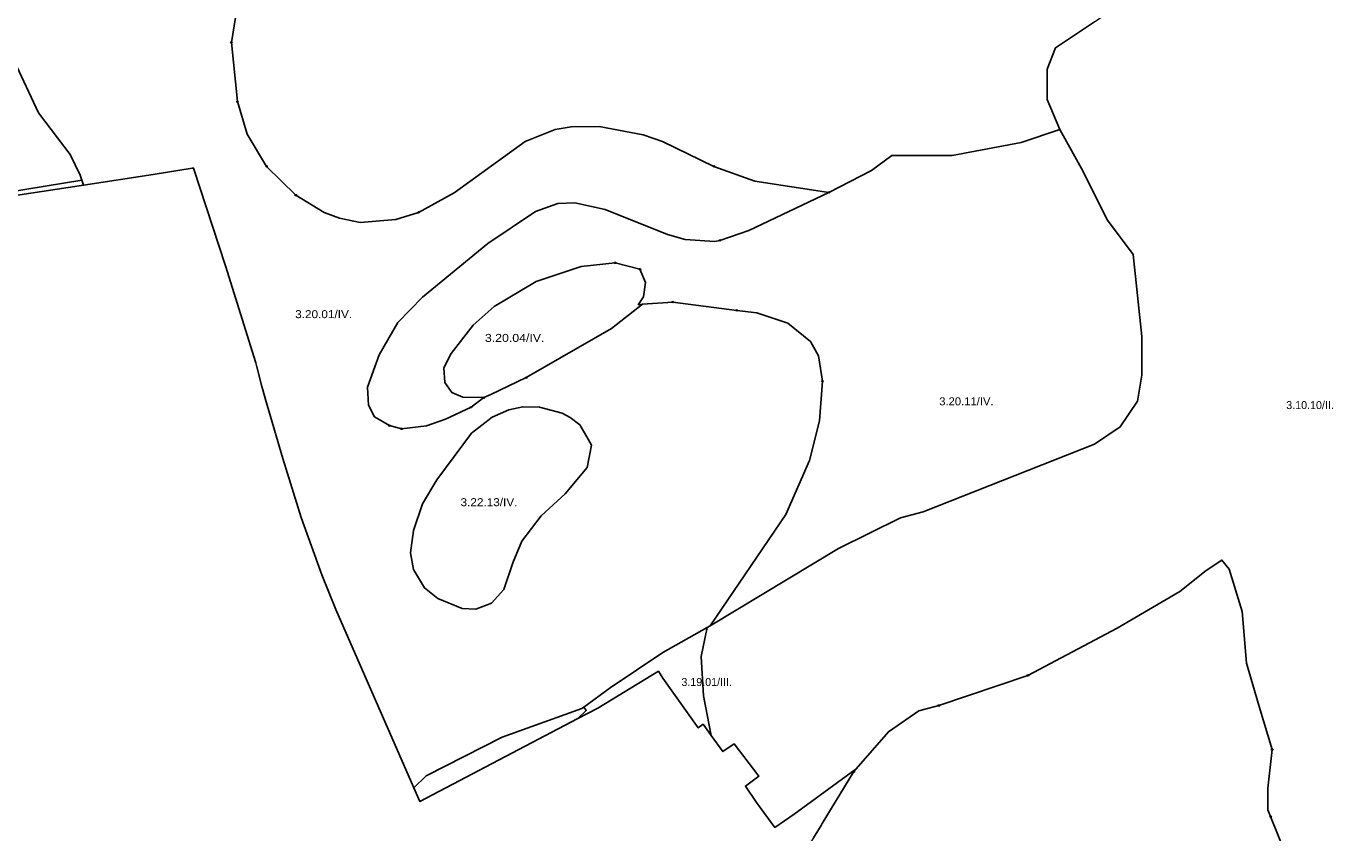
# Model space of a CAD drawing. Extents: x -650455 to -642254, y -1075222 to -1066610.
# Drawn here: x -649362 to -647729, y -1071216 to -1070208 of the extents above; entities that cross this region are included whole.
import ezdxf
from ezdxf.enums import TextEntityAlignment as Align

# ---------------------------------------------------------------- set-up
doc = ezdxf.new("R2010")
doc.units = 0
doc.header["$LTSCALE"] = 4
doc.header["$PDMODE"] = 32
doc.header["$PDSIZE"] = 2
for name, color, linetype, lineweight in [('1', 7, 'Continuous', 25), ('11', 7, 'Continuous', 13), ('12', 7, 'Continuous', 13), ('13', 7, 'Continuous', 13), ('14', 7, 'Continuous', 13)]:
    doc.layers.add(name, color=color, linetype=linetype, lineweight=lineweight)
doc.layers.add('2', color=7, linetype='Continuous')

msp = doc.modelspace()

# ---------------------------------------------------------------- linework, layer by layer
at = {"layer": '1'}
for points in [[(-649095, -1070162.5), (-649105.5, -1070228.001), (-649098, -1070302.001), (-649086, -1070342.501), (-649061.5, -1070383.001), (-649025, -1070419.001), (-648989.5, -1070440.5), (-648970.5, -1070447.501), (-648944.5, -1070453), (-648900, -1070449.5), (-648871.5, -1070440.5), (-648827, -1070416), (-648738.5, -1070352), (-648701, -1070337), (-648681, -1070333.501), (-648646, -1070333.001), (-648591, -1070343.5), (-648567, -1070352), (-648502.5, -1070383.001), (-648451.5, -1070401.5), (-648359, -1070415.501), (-648459, -1070463.001), (-648495, -1070475.501), (-648501.5, -1070477), (-648538.5, -1070474.5), (-648560.5, -1070468.001), (-648638.5, -1070437), (-648676.5, -1070428.5), (-648697.5, -1070429.5), (-648725.5, -1070439.501), (-648785, -1070479.501)], [(-648426.267, -1071209.383), (-648449.154, -1071178.032), (-648463.238, -1071157.601), (-648446.337, -1071145.271), (-648477.322, -1071104.762), (-648491.406, -1071114.625), (-648506.045, -1071094.331), (-648515.5, -1071045), (-648518.5, -1070995.5), (-648511, -1070959.5), (-648507.369, -1070957.309), (-648347, -1070860.501), (-648269.5, -1070822.5), (-648241, -1070815.001), (-648027.074, -1070730.177), (-647994.757, -1070708.632), (-647973.213, -1070676.315), (-647967.826, -1070643.998), (-647967.826, -1070595.523), (-647978.599, -1070493.186), (-648010.916, -1070450.096), (-648043.233, -1070385.463), (-648070.164, -1070336.987), (-648086.322, -1070299.284), (-648086.322, -1070261.581), (-648075.55, -1070234.65), (-648027.074, -1070202.333)], [(-649377, -1070251), (-649346.5, -1070316), (-649307, -1070368), (-649294.5, -1070394.001), (-649292.5, -1070400), (-649384, -1070415.001)], [(-649041.195, -1070748.176), (-649062.695, -1070674.37), (-649066.192, -1070662.363), (-649067.279, -1070658.191), (-649073.701, -1070633.531), (-649074.607, -1070630.05), (-649074.998, -1070628.551), (-649113.062, -1070507.22), (-649152.827, -1070384.991), (-649154.468, -1070385.26), (-649203.149, -1070393.237), (-649290.153, -1070406.417), (-649292.5, -1070400), (-649294.5, -1070394.001), (-649307, -1070368), (-649346.5, -1070316), (-649377, -1070251)], [(-648725.5, -1070439.501), (-648697.5, -1070429.5), (-648676.5, -1070428.5), (-648638.5, -1070437), (-648560.5, -1070468.001), (-648538.5, -1070474.5), (-648501.5, -1070477), (-648495, -1070475.501), (-648459, -1070463.001), (-648359, -1070415.501), (-648305.5, -1070388), (-648280.182, -1070369.304), (-648204.818, -1070369.304), (-648118.639, -1070353.145), (-648070.164, -1070336.987), (-648043.233, -1070385.463), (-648010.916, -1070450.096), (-647978.599, -1070493.186), (-647967.826, -1070595.523), (-647967.826, -1070643.998), (-647973.213, -1070676.315), (-647994.757, -1070708.632), (-648027.074, -1070730.177), (-648241, -1070815.001), (-648269.5, -1070822.5), (-648347, -1070860.501), (-648507.369, -1070957.309)], [(-648507.369, -1070957.309), (-648412.5, -1070818), (-648383, -1070750.501), (-648370.5, -1070701), (-648367, -1070651.5), (-648372, -1070620), (-648382, -1070602.001), (-648410, -1070579), (-648449, -1070566), (-648474, -1070563), (-648554, -1070552.501), (-648592, -1070555), (-648597, -1070556.001), (-648590.5, -1070546), (-648588, -1070528.001), (-648595, -1070511.501), (-648626, -1070503.501), (-648668.5, -1070508.001), (-648724.5, -1070527), (-648777, -1070558), (-648803.5, -1070581.501), (-648831, -1070617.001), (-648840, -1070635), (-648839, -1070653.001), (-648830, -1070665.501), (-648816.5, -1070671.5), (-648790, -1070672), (-648806, -1070684), (-648838, -1070699.001), (-648861.5, -1070707.5), (-648893, -1070711.001), (-648908, -1070707.001), (-648926.5, -1070696), (-648934, -1070681.501), (-648935.5, -1070659), (-648921, -1070618.5), (-648897.5, -1070578), (-648866.5, -1070546.5), (-648785, -1070479.501), (-648725.5, -1070439.501)], [(-648785, -1070479.501), (-648866.5, -1070546.5), (-648897.5, -1070578), (-648921, -1070618.5), (-648935.5, -1070659), (-648934, -1070681.501), (-648926.5, -1070696), (-648908, -1070707.001), (-648893, -1070711.001), (-648861.5, -1070707.5), (-648838, -1070699.001), (-648806, -1070684), (-648790, -1070672), (-648781.5, -1070668), (-648737, -1070647), (-648630.5, -1070585.501), (-648592, -1070555), (-648554, -1070552.501), (-648474, -1070563), (-648449, -1070566), (-648410, -1070579), (-648382, -1070602.001), (-648372, -1070620), (-648367, -1070651.5), (-648370.5, -1070701), (-648383, -1070750.501), (-648412.5, -1070818), (-648507.369, -1070957.309), (-648511, -1070959.5), (-648566.5, -1070990.501), (-648632, -1071035.001), (-648665, -1071059.001), (-648667.5, -1071060.5), (-648767, -1071096.5), (-648862, -1071145), (-648877.384, -1071160.07), (-648975.147, -1070936.986), (-648992.621, -1070893.659), (-649018.47, -1070821.77), (-649041.195, -1070748.176)], [(-647788.736, -1071241.189), (-647806.937, -1071195.687), (-647810.281, -1071187.327), (-647810.281, -1071160.397), (-647804.895, -1071111.921), (-647821.053, -1071058.06), (-647837.212, -1071004.198), (-647842.598, -1070939.564), (-647858.53, -1070886.459), (-647867.716, -1070875.174), (-647887.378, -1070888.282), (-647920.15, -1070914.5), (-647998.802, -1070960.38), (-648110.225, -1071019.369), (-648221.5, -1071057), (-648246.5, -1071063.501), (-648284.5, -1071090), (-648327.713, -1071139.525), (-648326.269, -1071137.169), (-648402.324, -1071192.827), (-648426.267, -1071209.383)], [(-648378.097, -1071222.492), (-648368.619, -1071206.983), (-648367.47, -1071204.399), (-648327.713, -1071139.525), (-648284.5, -1071090), (-648246.5, -1071063.501), (-648221.5, -1071057), (-648110.225, -1071019.369), (-647998.802, -1070960.38), (-647920.15, -1070914.5), (-647887.378, -1070888.282), (-647867.716, -1070875.174), (-647858.53, -1070886.459), (-647842.598, -1070939.564), (-647837.212, -1071004.198)], [(-647837.212, -1071004.198), (-647821.053, -1071058.06), (-647804.895, -1071111.921), (-647810.281, -1071160.397), (-647810.281, -1071187.327), (-647806.937, -1071195.687), (-647788.736, -1071241.189)]]:
    msp.add_lwpolyline(points, dxfattribs=at)
for points in [[(-649292.5, -1070400), (-649290.153, -1070406.417), (-649441.654, -1070429.367), (-649547.261, -1070444.531), (-649548.761, -1070444.745), (-649561.895, -1070448.418), (-649615.231, -1070460.576), (-649617.552, -1070460.168), (-649621.118, -1070460.078), (-649621.21, -1070460.1), (-649621, -1070441), (-649622.5, -1070387.501), (-649635.5, -1070354.001), (-649653, -1070326.501), (-649662, -1070295), (-649546, -1070342.501), (-649404.5, -1070412.5), (-649384, -1070415.001)], [(-648592, -1070555), (-648630.5, -1070585.501), (-648737, -1070647), (-648781.5, -1070668), (-648790, -1070672), (-648816.5, -1070671.5), (-648830, -1070665.501), (-648839, -1070653.001), (-648840, -1070635), (-648831, -1070617.001), (-648803.5, -1070581.501), (-648777, -1070558), (-648724.5, -1070527), (-648668.5, -1070508.001), (-648626, -1070503.501), (-648595, -1070511.501), (-648588, -1070528.001), (-648590.5, -1070546), (-648597, -1070556.001)], [(-648780.5, -1070929.001), (-648765, -1070912.001), (-648754, -1070878.5), (-648742.5, -1070851.501), (-648718.5, -1070820.001), (-648688.5, -1070792.5), (-648661, -1070759.501), (-648655.5, -1070731.501), (-648659.5, -1070724), (-648670, -1070706.001), (-648682, -1070697), (-648692, -1070691.5), (-648720.5, -1070684), (-648741.5, -1070683.5), (-648759, -1070687.5), (-648779.5, -1070696.5), (-648805.5, -1070716.5), (-648849, -1070775.001), (-648866.5, -1070805), (-648878, -1070838), (-648881.5, -1070866), (-648878, -1070887), (-648864, -1070910), (-648847.5, -1070923), (-648817, -1070935.5), (-648800, -1070936.501)], [(-648780.5, -1070929.001), (-648800, -1070936.501), (-648817, -1070935.5), (-648847.5, -1070923), (-648864, -1070910), (-648878, -1070887), (-648881.5, -1070866), (-648878, -1070838), (-648866.5, -1070805), (-648849, -1070775.001), (-648805.5, -1070716.5), (-648779.5, -1070696.5), (-648759, -1070687.5), (-648741.5, -1070683.5), (-648720.5, -1070684), (-648692, -1070691.5), (-648682, -1070697), (-648670, -1070706.001), (-648659.5, -1070724), (-648655.5, -1070731.501), (-648661, -1070759.501), (-648688.5, -1070792.5), (-648718.5, -1070820.001), (-648742.5, -1070851.501), (-648754, -1070878.5), (-648765, -1070912.001)], [(-648518.5, -1070995.5), (-648515.5, -1071045), (-648506.045, -1071094.331), (-648516.053, -1071080.457), (-648522.391, -1071084.685), (-648566.404, -1071022.688), (-648571.8, -1071014.049), (-648647.789, -1071060.362), (-648672.55, -1071073.359), (-648662, -1071063.001), (-648665, -1071059.001), (-648632, -1071035.001), (-648566.5, -1070990.501), (-648511, -1070959.5)], [(-648672.55, -1071073.359), (-648869.971, -1071176.986), (-648877.384, -1071160.07), (-648862, -1071145), (-648767, -1071096.5), (-648667.5, -1071060.5), (-648665, -1071059.001), (-648662, -1071063.001)]]:
    msp.add_lwpolyline(points, close=True, dxfattribs=at)
at = {"layer": '11'}
for p, q in [((-649105.5, -1070228.001), (-649098, -1070302.001)), ((-647788.736, -1071241.189), (-647806.937, -1071195.687))]:
    msp.add_line(p, q, dxfattribs=at)
for points in [[(-648819.5, -1069761), (-648791.5, -1069782), (-648774.5, -1069810), (-648769, -1069831.501), (-648772.5, -1069872.001), (-648781.5, -1069894.5), (-648808.5, -1069926), (-648853, -1069952.501), (-648883.5, -1069962.5), (-648919, -1069968.5), (-648912.614, -1070000), (-648911.5, -1070005.501), (-648918, -1070020.5), (-648942, -1070040), (-648979.5, -1070057), (-649008, -1070070.001), (-649053.5, -1070100.001), (-649085, -1070140.001), (-649095, -1070162.5), (-649105.5, -1070228.001)], [(-648359, -1070415.501), (-648305.5, -1070388), (-648280.182, -1070369.304), (-648204.818, -1070369.304), (-648118.639, -1070353.145), (-648070.164, -1070336.987), (-648086.322, -1070299.284), (-648086.322, -1070261.581), (-648075.55, -1070234.65), (-648027.074, -1070202.333), (-647998.797, -1070182.808)], [(-649098, -1070302.001), (-649086, -1070342.501), (-649061.5, -1070383.001), (-649025, -1070419.001)], [(-649025, -1070419.001), (-648989.5, -1070440.5), (-648970.5, -1070447.501), (-648944.5, -1070453), (-648900, -1070449.5), (-648871.5, -1070440.5), (-648827, -1070416), (-648738.5, -1070352), (-648701, -1070337), (-648681, -1070333.501), (-648646, -1070333.001), (-648591, -1070343.5), (-648567, -1070352), (-648502.5, -1070383.001)], [(-648502.5, -1070383.001), (-648451.5, -1070401.5), (-648359, -1070415.501)], [(-647804.895, -1071111.921), (-647821.053, -1071058.06), (-647837.212, -1071004.198), (-647842.598, -1070939.564), (-647858.53, -1070886.459), (-647867.716, -1070875.174), (-647887.378, -1070888.282), (-647920.15, -1070914.5), (-647998.802, -1070960.38), (-648110.225, -1071019.369)], [(-648110.225, -1071019.369), (-648221.5, -1071057), (-648246.5, -1071063.501), (-648284.5, -1071090), (-648327.713, -1071139.525)], [(-647806.937, -1071195.687), (-647810.281, -1071187.327), (-647810.281, -1071160.397), (-647804.895, -1071111.921)], [(-648327.713, -1071139.525), (-648367.47, -1071204.399), (-648368.619, -1071206.983), (-648378.097, -1071222.492), (-648386.713, -1071235.418), (-648397.483, -1071253.511), (-648410.551, -1071274.192), (-648413.28, -1071279.36), (-648415.434, -1071281.946), (-648421.035, -1071292.285), (-648502.316, -1071458.869), (-648515.528, -1071484.719), (-648550.69, -1071556.284)]]:
    msp.add_lwpolyline(points, dxfattribs=at)
at = {"layer": '11', "lineweight": 25}
for points in [[(-648280.182, -1070369.304), (-648305.5, -1070388), (-648359, -1070415.501), (-648451.5, -1070401.5), (-648502.5, -1070383.001), (-648567, -1070352), (-648591, -1070343.5), (-648646, -1070333.001), (-648681, -1070333.501), (-648701, -1070337), (-648738.5, -1070352), (-648827, -1070416), (-648871.5, -1070440.5), (-648900, -1070449.5), (-648944.5, -1070453), (-648970.5, -1070447.501), (-648989.5, -1070440.5), (-649025, -1070419.001), (-649061.5, -1070383.001), (-649086, -1070342.501), (-649098, -1070302.001), (-649105.5, -1070228.001), (-649095, -1070162.5)], [(-648027.074, -1070202.333), (-648075.55, -1070234.65), (-648086.322, -1070261.581), (-648086.322, -1070299.284), (-648070.164, -1070336.987), (-648118.639, -1070353.145), (-648204.818, -1070369.304), (-648280.182, -1070369.304)]]:
    msp.add_lwpolyline(points, dxfattribs=at)
at = {"layer": '11'}
for p in [(-649105.5, -1070228.001), (-649098, -1070302.001), (-648502.5, -1070383.001), (-649025, -1070419.001), (-648359, -1070415.501), (-648110.225, -1071019.369), (-647804.895, -1071111.921), (-648327.713, -1071139.525), (-647806.937, -1071195.687)]:
    msp.add_point(p, dxfattribs=at)
at = {"layer": '12'}
msp.add_line((-648221.5, -1071057), (-648110.225, -1071019.369), dxfattribs=at)
for points in [[(-648027.074, -1070202.333), (-648075.55, -1070234.65), (-648086.322, -1070261.581), (-648086.322, -1070299.284), (-648070.164, -1070336.987), (-648043.233, -1070385.463), (-648010.916, -1070450.096), (-647978.599, -1070493.186), (-647967.826, -1070595.523), (-647967.826, -1070643.998), (-647973.213, -1070676.315), (-647994.757, -1070708.632), (-648027.074, -1070730.177), (-648241, -1070815.001), (-648269.5, -1070822.5), (-648347, -1070860.501), (-648507.369, -1070957.309), (-648511, -1070959.5), (-648518.5, -1070995.5), (-648515.5, -1071045), (-648506.045, -1071094.331), (-648491.406, -1071114.625), (-648477.322, -1071104.762), (-648446.337, -1071145.271), (-648463.238, -1071157.601), (-648449.154, -1071178.032), (-648426.267, -1071209.383), (-648402.324, -1071192.827), (-648326.269, -1071137.169), (-648327.713, -1071139.525), (-648284.5, -1071090), (-648246.5, -1071063.501), (-648221.5, -1071057)], [(-648110.225, -1071019.369), (-647998.802, -1070960.38), (-647920.15, -1070914.5), (-647887.378, -1070888.282), (-647867.716, -1070875.174), (-647858.53, -1070886.459), (-647842.598, -1070939.564), (-647837.212, -1071004.198), (-647821.053, -1071058.06), (-647804.895, -1071111.921), (-647810.281, -1071160.397), (-647810.281, -1071187.327), (-647806.937, -1071195.687), (-647788.736, -1071241.189), (-647773.924, -1071271.486)]]:
    msp.add_lwpolyline(points, dxfattribs=at)
for p in [(-648110.225, -1071019.369), (-648221.5, -1071057)]:
    msp.add_point(p, dxfattribs=at)
at = {"layer": '13'}
for points in [[(-649621, -1070441), (-649621.21, -1070460.1), (-649621.118, -1070460.078), (-649617.552, -1070460.168), (-649615.231, -1070460.576), (-649561.895, -1070448.418), (-649548.761, -1070444.745), (-649547.261, -1070444.531), (-649441.654, -1070429.367), (-649290.153, -1070406.417), (-649292.5, -1070400), (-649384, -1070415.001), (-649404.5, -1070412.5), (-649546, -1070342.501), (-649662, -1070295), (-649653, -1070326.501), (-649635.5, -1070354.001), (-649622.5, -1070387.501)], [(-648522.391, -1071084.685), (-648516.053, -1071080.457), (-648506.045, -1071094.331), (-648515.5, -1071045), (-648518.5, -1070995.5), (-648511, -1070959.5), (-648566.5, -1070990.501), (-648632, -1071035.001), (-648665, -1071059.001), (-648662, -1071063.001), (-648672.55, -1071073.359), (-648647.789, -1071060.362), (-648571.8, -1071014.049), (-648566.404, -1071022.688)]]:
    msp.add_lwpolyline(points, close=True, dxfattribs=at)
at = {"layer": '14'}
for p, q in [((-648626, -1070503.501), (-648595, -1070511.501)), ((-648908, -1070707.001), (-648893, -1070711.001))]:
    msp.add_line(p, q, dxfattribs=at)
for points in [[(-649404.5, -1070412.5), (-649384, -1070415.001), (-649292.5, -1070400), (-649294.5, -1070394.001), (-649307, -1070368), (-649346.5, -1070316), (-649377, -1070251), (-649407, -1070205.5), (-649425.5, -1070192.501), (-649489.5, -1070169.5), (-649494, -1070169.5), (-649514, -1070154.5), (-649540, -1070127.501), (-649568, -1070064.5), (-649575, -1070037.501), (-649579, -1070001.001), (-649578.779, -1070000), (-649571.5, -1069967), (-649552.5, -1069920.501), (-649576, -1069863)], [(-649061.5, -1070383.001), (-649086, -1070342.501), (-649098, -1070302.001), (-649105.5, -1070228.001), (-649095, -1070162.5)], [(-649377, -1070251), (-649346.5, -1070316), (-649307, -1070368), (-649294.5, -1070394.001), (-649292.5, -1070400), (-649290.153, -1070406.417), (-649203.149, -1070393.237), (-649154.468, -1070385.26), (-649152.827, -1070384.991), (-649113.062, -1070507.22), (-649074.998, -1070628.551), (-649074.607, -1070630.05), (-649073.701, -1070633.531), (-649067.279, -1070658.191), (-649066.192, -1070662.363), (-649062.695, -1070674.37), (-649041.195, -1070748.176), (-649018.47, -1070821.77), (-648992.621, -1070893.659)], [(-648359, -1070415.501), (-648451.5, -1070401.5), (-648502.5, -1070383.001), (-648567, -1070352), (-648591, -1070343.5), (-648646, -1070333.001), (-648681, -1070333.501), (-648701, -1070337), (-648738.5, -1070352), (-648827, -1070416), (-648871.5, -1070440.5)], [(-648269.5, -1070822.5), (-648241, -1070815.001), (-648027.074, -1070730.177), (-647994.757, -1070708.632), (-647973.213, -1070676.315), (-647967.826, -1070643.998), (-647967.826, -1070595.523), (-647978.599, -1070493.186), (-648010.916, -1070450.096), (-648043.233, -1070385.463), (-648070.164, -1070336.987), (-648118.639, -1070353.145), (-648204.818, -1070369.304), (-648280.182, -1070369.304), (-648305.5, -1070388), (-648359, -1070415.501), (-648459, -1070463.001), (-648495, -1070475.501)], [(-648871.5, -1070440.5), (-648900, -1070449.5), (-648944.5, -1070453), (-648970.5, -1070447.501), (-648989.5, -1070440.5), (-649025, -1070419.001), (-649061.5, -1070383.001)], [(-648806, -1070684), (-648838, -1070699.001), (-648861.5, -1070707.5), (-648893, -1070711.001), (-648908, -1070707.001), (-648926.5, -1070696), (-648934, -1070681.501), (-648935.5, -1070659), (-648921, -1070618.5), (-648897.5, -1070578), (-648866.5, -1070546.5), (-648785, -1070479.501), (-648725.5, -1070439.501), (-648697.5, -1070429.5), (-648676.5, -1070428.5), (-648638.5, -1070437), (-648560.5, -1070468.001), (-648538.5, -1070474.5), (-648501.5, -1070477), (-648495, -1070475.501), (-648459, -1070463.001), (-648359, -1070415.501)], [(-648495, -1070475.501), (-648501.5, -1070477), (-648538.5, -1070474.5), (-648560.5, -1070468.001), (-648638.5, -1070437), (-648676.5, -1070428.5), (-648697.5, -1070429.5), (-648725.5, -1070439.501), (-648785, -1070479.501), (-648866.5, -1070546.5), (-648897.5, -1070578), (-648921, -1070618.5), (-648935.5, -1070659), (-648934, -1070681.501), (-648926.5, -1070696), (-648908, -1070707.001)], [(-648790, -1070672), (-648816.5, -1070671.5), (-648830, -1070665.501), (-648839, -1070653.001), (-648840, -1070635), (-648831, -1070617.001), (-648803.5, -1070581.501), (-648777, -1070558), (-648724.5, -1070527), (-648668.5, -1070508.001), (-648626, -1070503.501)], [(-648595, -1070511.501), (-648588, -1070528.001), (-648590.5, -1070546), (-648597, -1070556.001), (-648592, -1070555), (-648554, -1070552.501), (-648474, -1070563)], [(-648992.621, -1070893.659), (-648975.147, -1070936.986), (-648877.384, -1071160.07), (-648862, -1071145), (-648767, -1071096.5), (-648667.5, -1071060.5), (-648665, -1071059.001), (-648632, -1071035.001), (-648566.5, -1070990.501), (-648511, -1070959.5), (-648507.369, -1070957.309), (-648412.5, -1070818), (-648383, -1070750.501), (-648370.5, -1070701), (-648367, -1070651.5), (-648372, -1070620), (-648382, -1070602.001), (-648410, -1070579), (-648449, -1070566), (-648474, -1070563), (-648554, -1070552.501)], [(-648554, -1070552.501), (-648592, -1070555), (-648630.5, -1070585.501), (-648737, -1070647)], [(-648474, -1070563), (-648449, -1070566), (-648410, -1070579), (-648382, -1070602.001), (-648372, -1070620), (-648367, -1070651.5)], [(-648737, -1070647), (-648781.5, -1070668), (-648790, -1070672), (-648806, -1070684)], [(-648367, -1070651.5), (-648370.5, -1070701), (-648383, -1070750.501), (-648412.5, -1070818), (-648507.369, -1070957.309), (-648347, -1070860.501), (-648269.5, -1070822.5)], [(-648893, -1070711.001), (-648861.5, -1070707.5), (-648838, -1070699.001), (-648806, -1070684), (-648790, -1070672)]]:
    msp.add_lwpolyline(points, dxfattribs=at)
msp.add_lwpolyline([(-648790, -1070672), (-648781.5, -1070668), (-648737, -1070647), (-648630.5, -1070585.501), (-648592, -1070555), (-648597, -1070556.001), (-648590.5, -1070546), (-648588, -1070528.001), (-648595, -1070511.501), (-648626, -1070503.501), (-648668.5, -1070508.001), (-648724.5, -1070527), (-648777, -1070558), (-648803.5, -1070581.501), (-648831, -1070617.001), (-648840, -1070635), (-648839, -1070653.001), (-648830, -1070665.501), (-648816.5, -1070671.5)], close=True, dxfattribs=at)
for p in [(-649061.5, -1070383.001), (-648359, -1070415.501), (-648871.5, -1070440.5), (-648495, -1070475.501), (-648626, -1070503.501), (-648595, -1070511.501), (-648554, -1070552.501), (-648474, -1070563), (-648737, -1070647), (-648367, -1070651.5), (-648790, -1070672), (-648806, -1070684), (-648908, -1070707.001), (-648893, -1070711.001)]:
    msp.add_point(p, dxfattribs=at)

# ---------------------------------------------------------------- texts
at = {"layer": '2'}
for s, width, p in [('3.20.01/IV.', 1.1, (-648990.227, -1070572.697)), ('3.20.04/IV.', 1.15, (-648751.51, -1070602.391)), ('3.20.11/IV.', 1.05, (-648187.047, -1070681.68)), ('3.22.13/IV.', 1.1, (-648783.617, -1070807.776))]:
    msp.add_text(s, height=10, dxfattribs=dict(at, width=width)).set_placement(p, align=Align.CENTER)
for s, p in [('3.10.10/II.', (-647757.632, -1070686.349)), ('3.19.01/III.', (-648511.598, -1071032.607))]:
    msp.add_text(s, height=10, dxfattribs=at).set_placement(p, align=Align.CENTER)

doc.saveas('drawing.dxf')
